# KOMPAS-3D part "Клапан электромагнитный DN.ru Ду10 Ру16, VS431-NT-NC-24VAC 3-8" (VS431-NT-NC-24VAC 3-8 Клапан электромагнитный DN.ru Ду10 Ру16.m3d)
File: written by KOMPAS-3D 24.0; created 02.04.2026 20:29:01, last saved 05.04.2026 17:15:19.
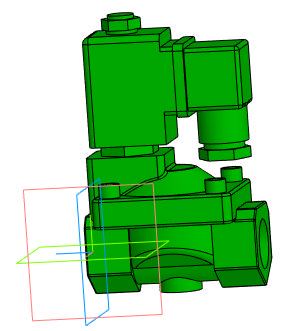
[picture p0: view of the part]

Document properties: Автор: artio; Полное имя файла: C:\Users\artio\OneDrive\Рабочий стол\Клапан электромагнитный DN.ru\VS431\VS431-NT-NC\VS431-NT-NC-24VAC\Ду10\VS431-NT-NC-24VAC 3-8 Клапан электромагнитный DN.ru Ду10 Ру16.m3d

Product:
- Body: Тело 1  | qty 1
    Масса: 1.030062
- Part/product: Клапан электромагнитный DN.ru Ду10 Ру16  | designation VS431-NT-NC-24VAC 3-8
    Масса: 0.62
    Раздел спецификации: Прочие изделия
    Примечание: D130-05636
    additional columns: ef56311e-7521-43dc-8291-0e6108b3d81d; VS400-ET-NC-220VAC 3-8; artio; c; Шероховатость не задана; Да

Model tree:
1. Операция без истории:1

Expressions: VS431-NT-NC-24VAC 3-8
